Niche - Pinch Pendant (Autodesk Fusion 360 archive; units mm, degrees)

design "Pinch" references "Luxe Single Pendant Cordset - 4ft Standard", "Niche - Chief Architect - Luxe Single Pendant Cordset", "Pinch"
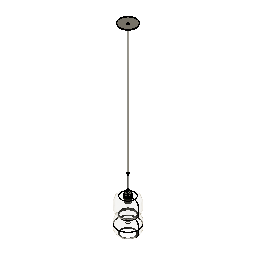
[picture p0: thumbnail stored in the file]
external_derived "ExternalDerived1"
external_derived "ExternalDerived2" bodies "Socket Body", "Shade Ring", "Shade Ring +Collar", "Socket", "Body1 (1)", "Metal Strain Relief", "Fabric Cord (1)", "Stem (Threaded)"
move "Move1"
external_derived "ExternalDerived3" bodies "T9-Bulb"
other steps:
derived_base_feature "Derived Base Feature1" bodies "Body1"
derived_base_feature "Derived Base Feature2" bodies "Socket Body", "Shade Ring", "Shade Ring +Collar", "Socket", "Body1 (1)", "Metal Strain Relief", "Fabric Cord (1)", "Stem (Threaded)"
derived_base_feature "Derived Base Feature3" bodies "T9-Bulb"
named bodies: "Body1", "Socket Body", "Shade Ring", "Shade Ring +Collar", "Socket", "Body1 (1)", "Metal Strain Relief", "Fabric Cord (1)", "Stem (Threaded)", "Cap (Threaded)", "T9-Bulb"

design "Luxe Single Pendant Cordset - 4ft Standard" references "Luxe Canopy - Single Pendant Cordset"
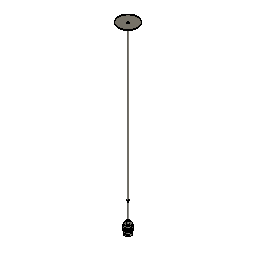
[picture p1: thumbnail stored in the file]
external_derived "ExternalDerived2" bodies "Cap (Threaded)"
move "Move1"
move "Move2"
offset_faces "OffsetFaces1" distance 1051.56
move "Move3"
move "Move4"
move "Move5"
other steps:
derived_base_feature "Derived Base Feature9" bodies "Socket Body", "Shade Ring", "Shade Ring +Collar", "Socket"
derived_base_feature "Derived Base Feature10" bodies "Body1"
derived_base_feature "Derived Base Feature12" bodies "Metal Strain Relief"
derived_base_feature "Derived Base Feature13" bodies "Fabric Cord (1)"
derived_base_feature "Derived Base Feature14" bodies "Stem (Threaded)"
derived_base_feature "Derived Base Feature15" bodies "Cap 9Threaded)", "Cap (Threaded)"
named bodies: "Socket Body", "Shade Ring", "Shade Ring +Collar", "Socket", "Metal Strain Relief", "Fabric Cord (1)", "Stem (Threaded)", "Cap 9Threaded)", "Body1", "Cap (Threaded)", "5M Set Screw"

design "Luxe Canopy - Single Pendant Cordset" references "Luxe Cordset", "M5 Set Screw", "Plastic Strain Relief", "Canopy Mounting Bar", "Canopy Mounting Bar Screw"
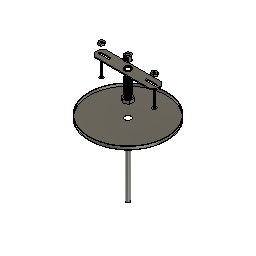
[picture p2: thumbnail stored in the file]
sketch "Sketch1" plane through (0, 0, 0) normal (0, 0, 1) x axis (1, 0, 0)
  circle C1 centre (0, 0) radius 63.5
  point P1 (0, 0)
  point P2 (0, 0)
  coincident P1 P2
  dimension "d1" diameter C1 = 127
extrude "Extrude1" new body sketch "Sketch1" along normal blind 5.08
shell "Shell1" innerThickness 0.762
hole "Hole1" HoleDepth 35.56 HoleDiameter 10.16 TipAngle 118
component_from_bodies "Body->Comp1"
component_insert "Component Insert1"
component_insert "Component Insert2"
component_insert "Component Insert3"
sketch "Sketch2" plane through (0, 0, 0) normal (0, 0, 1) x axis (1, 0, 0)
  circle C1 centre (0, 0) radius 3.175
  point P1 (0, 0)
  point P2 (0, 0)
  coincident P1 P2
  dimension "d8" diameter C1 = 6.35
extrude "Extrude2" new body sketch "Sketch2" along normal blind 127 and against normal blind 127 bodies "Fabric Cord"
component_insert "Component Insert4"
component_insert "Component Insert5"
position "Position1"
sketch "Sketch3" plane through (0, 0, 0.762) normal (0, 0, 1) x axis (-1, 0, 0)
  circle C1 centre (-0.0475, 0.2257) radius 5.08
  circle C2 centre (0, 0) radius 62.738
  circle C3 centre (0, 0) radius 4.826
  concentric C2 C3
  dimension "d13" diameter C3 = 9.652
extrude "Extrude3" new body sketch "Sketch3" profile of C3 along normal blind 25.4 bodies "Threaded Nipple"
shell "Shell2" innerThickness 1.27
thread "Thread1"
sketch "Sketch5" plane through (0, 0, 127) normal (0, 0, 1) x axis (-1, 0, 0)
  line L1 (-6.8191, 3.937) -> (0, 7.874)
  line L2 (-6.8191, -3.937) -> (-6.8191, 3.937)
  line L3 (0, -7.874) -> (-6.8191, -3.937)
  line L4 (6.8191, -3.937) -> (0, -7.874)
  line L5 (6.8191, 3.937) -> (6.8191, -3.937)
  line L6 (0, 7.874) -> (6.8191, 3.937)
  circle C1 centre (0, 0) radius 3.175
  point P2 (0, 0)
  point P9 (0, 0)
  point P3 (0, 7.874)
  coincident P2 P9
  dimension "d20" distance P3 P9 = 7.874
extrude "Extrude4" new body sketch "Sketch5" along normal blind 5.08 bodies "Hex Nut"
move "Move1"
thread "Thread2"
move "Move2" TranslateX 0 TranslateY 0 TranslateZ -55.88
move "Move3" TranslateX 0 TranslateY 0 TranslateZ 60.96
position "Position2"
sketch "Sketch6" plane through (0, 0, 0) normal (0, 0, 1) x axis (1, 0, 0)
  circle C1 centre (0, 0) radius 9.525
  point P1 (0, 0)
  point P2 (0, 0)
  coincident P1 P2
  dimension "d29" diameter C1 = 19.05
extrude "Extrude5" new body sketch "Sketch6" along normal blind 16.129 bodies "Metal Strain Relief"
move "Move4" TranslateX 0 TranslateY 0 TranslateZ -86.36
hole "Hole2" HoleDepth 10.16 HoleDiameter 5.08 TipAngle 118
hole "Hole3" HoleDepth 4.064 HoleDiameter 7.62 TipAngle 180
hole "Hole4" HoleDepth 12.192 HoleDiameter 9.144 TipAngle 180
thread "Thread3" ThreadOffset 0 ThreadLength 6.096
move "Move1" TranslateX 0 TranslateY 0 TranslateZ 68.58
move "Move5" TranslateX 0 TranslateY 0 TranslateZ 138.43
component_insert "Component Insert6"
external_derived "ExternalDerived1" bodies "5M Set Screw"
move "Move6" TranslateX 0 TranslateY 0 TranslateZ -185.42
copy_paste_bodies "CopyPasteBodies1"
move "Move7" TranslateX 0 TranslateY 0 TranslateZ -12.7
offset_faces "OffsetFaces1" distance -152.4
move "Move8"
component_from_bodies "Body->Comp2"
component_from_bodies "Body->Comp3"
component_from_bodies "Body->Comp4"
component_from_bodies "Body->Comp5"
hole "Hole1" HoleDepth 25.4 HoleDiameter 6.35 TipAngle 180
sketch "Sketch7" plane through (0, 0, 0) normal (0, 0, 1) x axis (1, 0, 0)
  line L1 (49.784, 3.9595) -> (52.07, 0)
  line L2 (45.212, 3.9595) -> (49.784, 3.9595)
  line L3 (42.926, 0) -> (45.212, 3.9595)
  line L4 (45.212, -3.9595) -> (42.926, 0)
  line L5 (49.784, -3.9595) -> (45.212, -3.9595)
  line L6 (52.07, 0) -> (49.784, -3.9595)
  point P2 (52.07, 0)
  point P8 (47.498, 0)
  dimension "d63" distance P2 P8 = 4.572
extrude "Extrude6" new body sketch "Sketch7" along normal blind 3.175 bodies "Mounting Hex Nut"
hole "Hole5" HoleDepth 25.4 HoleDiameter 3.81 TipAngle 180
thread "Thread4"
move "Move9"
component_from_bodies "Body->Comp6"
copy_paste "CopyPaste1"
move "Move10"
derived_base_feature "Derived Base Feature3" bodies "Stem (Threaded)", "Cap 9Threaded)"
move "Move11"
component_from_bodies "Body->Comp7"
component_from_bodies "Body->Comp8"
component_from_bodies "Body->Comp9"
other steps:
base_feature "Base Feature1"
base_feature "Base Feature1" bodies "Stem (Threaded)"
base_feature "Base Feature1" bodies "Cap 9Threaded)"
base_feature "Base Feature1" bodies "Fabric Cord"
base_feature "Base Feature1" bodies "Metal Strain Relief"
base_feature "Base Feature1" bodies "Mounting Hex Nut"
base_feature "Base Feature1" bodies "Hex Nut"
base_feature "Base Feature1" bodies "Fabric Cord (1)"
base_feature "Base Feature1" bodies "Threaded Nipple"
derived_base_feature "Derived Base Feature1" bodies "Socket Body", "Shade Ring", "Shade Ring +Collar", "Socket", "Rigid Stem"
derived_base_feature "Derived Base Feature2" bodies "5M Set Screw"
base_feature "Base Feature1" bodies "Fabric Cord", "Fabric Cord (1)"
create_component "CreateComponent1"
remove_body "RemoveBody1"
create_component "CreateComponent2"
remove_body "RemoveBody2"
create_component "CreateComponent3"
remove_body "RemoveBody3"
create_component "CreateComponent4"
remove_body "RemoveBody4"
create_component "CreateComponent5"
remove_body "RemoveBody5"
create_component "CreateComponent6"
remove_body "RemoveBody6"
create_component "CreateComponent7"
remove_body "RemoveBody7"
create_component "CreateComponent8"
remove_body "RemoveBody8"
create_component "CreateComponent9"
remove_body "RemoveBody9"
named bodies: "Fabric Cord", "Threaded Nipple", "Hex Nut", "Metal Strain Relief", "Socket Body", "Shade Ring", "Shade Ring +Collar", "Socket", "Rigid Stem", "5M Set Screw", "Fabric Cord (1)", "Mounting Hex Nut", "Stem (Threaded)", "Cap 9Threaded)"

design "M5 Set Screw"
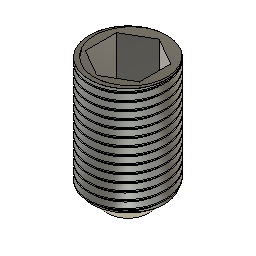
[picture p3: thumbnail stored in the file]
sketch "Sketch1" plane through (0, 0, 0) normal (0, 0, 1) x axis (1, 0, 0)
  circle C1 centre (0, 0) radius 2.5
  point P1 (0, 0)
  point P2 (0, 0)
  coincident P1 P2
  dimension "d1" diameter C1 = 5
extrude "Extrude1" new body sketch "Sketch1" along normal blind 8
sketch "Sketch2" plane through (0, 0, 8) normal (0, 0, 1) x axis (-1, 0, 0)
  line L1 (-1.7321, 1) -> (0, 2)
  line L2 (-1.7321, -1) -> (-1.7321, 1)
  line L3 (0, -2) -> (-1.7321, -1)
  line L4 (1.7321, -1) -> (0, -2)
  line L5 (1.7321, 1) -> (1.7321, -1)
  line L6 (0, 2) -> (1.7321, 1)
  circle C1 centre (0, 0) radius 2.5
  point P2 (0, 0)
  point P9 (0, 0)
  coincident P2 P9
extrude "Extrude2" cut sketch "Sketch2" profile of L1 L2 L3 L4 L5 L6 against normal blind 3
thread "Thread1" ThreadOffset 0.99 ThreadLength 7
chamfer "Chamfer1" distance 1.15

design "Luxe Cordset" references "M5 Set Screw"
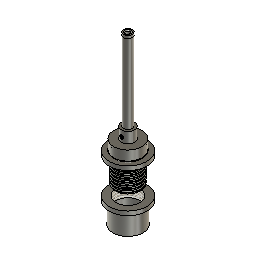
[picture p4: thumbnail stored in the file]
sketch "Sketch1" plane through (0, 0, 0) normal (0, 0, 1) x axis (1, 0, 0)
  circle C1 centre (0, 0) radius 20.6
  point P1 (0, 0)
  point P2 (0, 0)
  coincident P1 P2
  dimension "d11" diameter C1 = 41.2
extrude "Extrude1" new body sketch "Sketch1" along normal blind 14 bodies "Socket Body"
sketch "Sketch2" plane through (0, 0, 14) normal (0, 0, 1) x axis (-1, 0, 0)
  circle C1 centre (0, 0) radius 20.6
  circle C2 centre (0, 0) radius 9.6
  concentric C1 C2
  dimension "d3" diameter C2 = 19.2
extrude "Extrude2" add sketch "Sketch2" profile of C2 along normal blind 15.75
sketch "Sketch3" plane through (0, 0, 29.75) normal (0, 0, 1) x axis (-1, 0, 0)
  circle C1 centre (0, 0) radius 9.6
  circle C2 centre (0, 0) radius 5.75
  concentric C1 C2
  dimension "d6" diameter C2 = 11.5
extrude "Extrude3" new body sketch "Sketch3" profile of C2 along normal blind 114 bodies "Rigid Stem"
move "Move1"
sketch "Sketch4" plane through (0, 0, 203.75) normal (0, 0, 1) x axis (-1, 0, 0)
  circle C1 centre (0, 0) radius 5.75
  circle C2 centre (0, 0) radius 27.5
  dimension "d10" diameter C2 = 55
extrude "Extrude4" new body sketch "Sketch4" profile of C2 along normal blind 6 bodies "Shade Ring"
hole "Hole1" HoleDepth 25 HoleDiameter 42.75 TipAngle 118
sketch "Sketch5" plane through (0, 0, 0) normal (0, 0, 1) x axis (1, 0, 0)
  circle C1 centre (0, 0) radius 22
  point P1 (0, 0)
  point P2 (0, 0)
  coincident P1 P2
  dimension "d18" diameter C1 = 44
move "Move2"
copy_paste_bodies "CopyPasteBodies1"
move "Move3"
sketch "Sketch6" plane through (0, 0, 60) normal (0, 0, -1) x axis (1, 0, 0)
  circle C1 centre (0, 0) radius 20.6
  circle C2 centre (0, 0) radius 21.375
  circle C3 centre (0, 0) radius 20
  concentric C1 C2
  concentric C1 C3
  dimension "d21" diameter C2 = 42.75
  dimension "d24" diameter C3 = 40
cylinder_primitive "CylinderPrimitive1" Height 8 Diameter 42.75
thread "Thread1"
thread "Thread3"
hole "Hole2" HoleDepth 18 HoleDiameter 39 TipAngle 180
move "Move4"
move "Move5"
move "Move6"
hole "Hole3" HoleDepth 114 HoleDiameter 7.6 TipAngle 180
derived_base_feature "Derived Base Feature" bodies "Socket"
move "Move7"
scale "Scale1" ScaleX 1.2 ScaleY 1.2
move "Move8"
sketch "Sketch8" plane through (0, 0, -23.9827) normal (0, 0, -1) x axis (1, 0, 0)
  circle C1 centre (0, -0.036) radius 27.5
  circle C2 centre (0, -0.036) radius 22
  circle C3 centre (0, -0.036) radius 19.5
  dimension "d36" diameter C2 = 44
  dimension "d42" = -2.5
extrude "Extrude7" add sketch "Sketch8" profile of C2 C3 along normal blind 30
offset_faces "OffsetFaces1" distance 2.75
offset_faces "OffsetFaces2" distance -9
thread "Thread2"
move "Move9"
move "Move10"
move "Move11"
scale "Scale2" ScaleZ 1.2
move "Move12"
move "Move13"
move "Move14"
move "Move15"
move "Move16"
split_face "SplitFace1"
move "Move17"
move "Move18"
move "Move19"
move "Move20"
move "Move21"
move "Move22"
move "Move23"
move "Move24"
move "Move25"
move "Move26"
move "Move27"
thread "Thread4"
move "Move28"
move "Move29"
move "Move30"
hole "Hole4" HoleDepth 21 HoleDiameter 39.35 TipAngle 180
hole "Hole5" HoleDepth 9 HoleDiameter 5 TipAngle 180
move "Move31"
move "Move32"
hole "Hole6" HoleDepth 20 HoleDiameter 10 TipAngle 180
move_face "MoveFace3"
move "Move33"
move "Move34"
move "Move35"
move "Move36"
move "Move37"
thread "Thread5" ThreadOffset 0 ThreadLength 6
thread "Thread6" ThreadOffset 0 ThreadLength 6
move "Move38"
move "Move39"
move "Move40"
move "Move41"
component_insert "Component Insert"
thread "Thread7" ThreadOffset 0.5 ThreadLength 5.337
chamfer "Chamfer1" distance 0.5 distance 0.35
sketch "Sketch12" plane through (0, 0, 0) normal (0, 0, 1) x axis (1, 0, 0)
  circle C1 centre (0, 0) radius 6.35
  dimension "d60" diameter C1 = 12.7
extrude "Extrude8" new body sketch "Sketch12" along normal blind 115 bodies "Stem (Threaded)"
hole "Hole7" HoleDepth 115 HoleDiameter 9.65 TipAngle 118
thread "Thread8" ThreadOffset 0 ThreadLength 12.5
thread "Thread9" ThreadOffset 0 ThreadLength 12.5
sketch "Sketch13" plane through (0, 0, 0) normal (0, 0, 1) x axis (1, 0, 0)
  circle C1 centre (0, 0) radius 6.35
  point P1 (0, 0)
  point P2 (0, 0)
  coincident P1 P2
  dimension "d70" diameter C1 = 12.7
extrude "Extrude9" new body sketch "Sketch13" along normal blind 4 bodies "Cap 9Threaded)"
sketch "Sketch14" plane through (0, 0, 4) normal (0, 0, 1) x axis (-1, 0, 0)
  circle C1 centre (0, 0) radius 6.35
  circle C2 centre (0, 0) radius 4.5
  concentric C1 C2
  dimension "d73" diameter C2 = 9
extrude "Extrude10" add sketch "Sketch14" profile of C2 against normal blind 14
thread "Thread10"
hole "Hole8" HoleDepth 115 HoleDiameter 6.5 TipAngle 118 CSDiameter 9 CSAngle 90
move "Move42"
move "Move43"
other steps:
base_feature "Base Feature" bodies "Shade Ring +Collar"
named bodies: "Socket Body", "Shade Ring", "Shade Ring +Collar", "Socket", "Rigid Stem", "Stem (Threaded)", "Cap 9Threaded)"

design "Niche_Pinch_Single_Pendant"
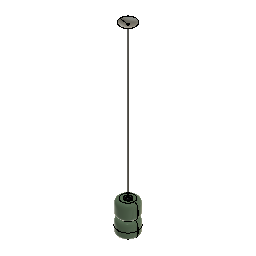
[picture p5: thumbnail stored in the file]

design "Niche - Chief Architect - Luxe Single Pendant Cordset"
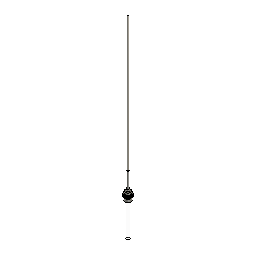
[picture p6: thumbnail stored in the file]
derived_base_feature "Derived Base Feature" bodies "Socket Body", "Shade Ring", "Shade Ring +Collar", "Socket", "Canopy", "Metal Strain Relief", "Fabric Cord (1)", "Stem (Threaded)"
remove_body "RemoveBody1"
remove_body "RemoveBody2"
split "Split1" bodies "Socket Body (1)"
remove_body "RemoveBody3"
align "Align1"
hole "Hole1" HoleDepth 19.05 HoleDiameter 8.89 TipAngle 118
combine "Combine1" bodies "Shade Ring"
split "Split2" bodies "Socket (1)"
remove_body "RemoveBody4"
split "Split3" bodies "Fabric Cord (1) (1)"
remove_body "RemoveBody5"
combine "Combine2" bodies "Socket Body"
align "Align2"
combine "Combine3" bodies "Metal Strain Relief"
sketch "Sketch1" plane through (0, 0, 0) normal (0, 1, 0) x axis (1, 0, 0)
  line L1 (13.1098, 24.9049) -> (-12.2902, 24.9049)
  line L2 (18.1898, 37.1766) -> (18.1898, 29.9849)
  line L3 (-17.3702, 29.9849) -> (-17.3702, 36.7132)
  line L4 (0, 132.969) -> (0, 24.9049)
  arc A1 centre (0, 86.36) radius 46.609 clockwise from (-22.6031, 45.5985) to (23.276, 45.979)
  arc A2 centre (-27.5302, 36.7132) radius 10.16 clockwise from (-22.6031, 45.5985) to (-17.3702, 36.7132)
  arc A3 centre (28.3498, 37.1766) radius 10.16 clockwise from (18.1898, 37.1766) to (23.276, 45.979)
  arc A4 centre (-12.2902, 29.9849) radius 5.08 clockwise from (-12.2902, 24.9049) to (-17.3702, 29.9849)
  arc A5 centre (13.1098, 29.9849) radius 5.08 clockwise from (18.1898, 29.9849) to (13.1098, 24.9049)
  point P5 (18.1898, 43.4469)
  point P3 (-17.3702, 24.9049)
  point P4 (18.1898, 24.9049)
  point P18 (0, 24.9049)
  point P19 (0, 132.969)
  horizontal L1
  vertical L2
  vertical L3
  tangent A1 A2
  tangent L3 A2
  coincident P5 L2
  coincident P5 A1
  tangent L2 A3
  tangent A1 A3
  equal A2 A3
  coincident P3 L1
  coincident P3 L3
  tangent L1 A4
  tangent L3 A4
  coincident P4 L1
  coincident P4 L2
  tangent L1 A5
  tangent L2 A5
  coincident L1 P18
  coincident A1 P19
  perpendicular L1 L4
  dimension "d4" diameter A1 = 93.218
  dimension "d5" distance P3 P4 = 35.56
  dimension "d6" distance P4 P5 = 18.542
  dimension "d7" radius A2 = 10.16
  dimension "d8" radius A4 = 5.08
  dimension "d9" radius A5 = 5.08
revolve "Revolve1" sketch "Sketch1" AlongAngle 360 bodies "G30-Bulb"
move "Move1"
sketch "Sketch2" plane through (0, 0, 0) normal (0, 1, 0) x axis (1, 0, 0)
  line L1 (12.7, 0) -> (-12.7, 0)
  line L2 (12.7, 152.4) -> (12.7, 0)
  line L3 (-12.7, 0) -> (-12.7, 152.4)
  line L4 (0, 165.1) -> (0, 0)
  arc A1 centre (0, 152.4) radius 12.7 clockwise from (-12.7, 152.4) to (12.7, 152.4)
  point P1 (0, 0)
  point P7 (0, 0)
  point P8 (0, 165.1)
  horizontal L1
  vertical L2
  vertical L3
  coincident P1 P7
  midpoint A1 P8
  perpendicular L1 L4
revolve "Revolve2" sketch "Sketch2" AlongAngle 360 bodies "T9-Bulb"
move "Move2"
sketch "Sketch3" plane through (0, 0, 0) normal (0, 1, 0) x axis (1, 0, 0)
  line L1 (12.7, 0) -> (-12.7, 0)
  line L2 (12.7, 254) -> (12.7, 0)
  line L3 (-12.7, 0) -> (-12.7, 254)
  line L4 (0, 266.7) -> (0, 0)
  arc A1 centre (0, 254) radius 12.7 clockwise from (-12.7, 254) to (12.7, 254)
  point P1 (0, 0)
  point P7 (0, 0)
  point P8 (0, 266.7)
  horizontal L1
  vertical L2
  vertical L3
  coincident P1 P7
  midpoint A1 P8
  perpendicular L1 L4
revolve "Revolve3" sketch "Sketch3" AlongAngle 360 bodies "T8-Bulb"
move "Move3"
move "Move4"
move "Move5"
sketch "Sketch4" plane through (0, 0, 0) normal (0, 1, 0) x axis (1, 0, 0)
  line L1 (15.875, -8.763) -> (-15.875, -8.763)
  line L2 (15.875, 22.987) -> (15.875, -8.763)
  line L3 (-15.875, 22.987) -> (15.875, 22.987)
  line L4 (-15.875, -8.763) -> (-15.875, 22.987)
  line L5 (0, 22.987) -> (0, -8.763)
  point P6 (0, -8.763)
  point P7 (0, 22.987)
  point P2 (-15.875, -8.763)
  point P3 (15.875, -8.763)
  point P5 (-15.875, 22.987)
  horizontal L1
  vertical L2
  horizontal L3
  vertical L4
  midpoint L1 P6
  midpoint L3 P7
  dimension "d13" distance P2 P3 = 31.75
  dimension "d14" distance P2 P5 = 31.75
revolve "Revolve4" sketch "Sketch4" AlongAngle 360 bodies "Bulb Extender"
move "Move6"
sketch "Sketch5" plane through (0, 0, 0) normal (0, 1, 0) x axis (1, 0, 0)
  line L1 (-12.7, 35.56) -> (12.7, 35.56)
  line L2 (-12.7, 5.08) -> (-12.7, 35.56)
  line L3 (12.7, 5.08) -> (-12.7, 5.08)
  line L4 (12.7, 35.56) -> (12.7, 5.08)
  line L5 (-12.7, 5.08) -> (12.7, 35.56)
  line L6 (12.7, 5.08) -> (-12.7, 35.56)
  line L7 (0, 35.56) -> (0, 5.08)
  point P6 (0, 20.32)
  point P7 (0, 5.08)
  point P8 (0, 35.56)
  horizontal L1
  perpendicular L1 L2
  parallel L1 L3
  parallel L2 L4
  coincident L5 P6
  coincident L6 P6
  midpoint L3 P7
  midpoint L1 P8
revolve "Revolve5" sketch "Sketch5" AlongAngle 360 bodies "Y-Spliter"
sketch "Sketch6" plane through (0, 0, 0) normal (0, 1, 0) x axis (1, 0, 0)
  line L1 (-55.88, 64.9514) -> (-21.59, 64.9514)
  line L2 (-55.88, 35.7414) -> (-55.88, 64.9514)
  line L3 (-21.59, 35.7414) -> (-55.88, 35.7414)
  line L4 (-21.59, 64.9514) -> (-21.59, 35.7414)
  line L5 (-55.88, 35.7414) -> (-21.59, 64.9514)
  line L6 (-21.59, 35.7414) -> (-55.88, 64.9514)
  line L7 (-38.735, 64.9514) -> (-38.735, 35.7414)
  point P6 (-38.735, 50.3464)
  point P7 (-38.735, 35.7414)
  point P8 (-38.735, 64.9514)
  point P4 (-55.88, 35.7414)
  point P5 (-21.59, 35.7414)
  point P2 (-21.59, 64.9514)
  horizontal L1
  perpendicular L1 L2
  parallel L1 L3
  parallel L2 L4
  coincident L5 P6
  coincident L6 P6
  midpoint L3 P7
  midpoint L1 P8
  dimension "d17" distance P4 P5 = 34.29
  dimension "d18" distance P2 P5 = 29.21
revolve "Revolve6" sketch "Sketch6" AlongAngle 360
chamfer "Chamfer1" distance 7.62
move "Move7"
mirror "Mirror1" mirrorStitchTolerance 0.1016
move "Move8"
combine "Combine4"
move "Move9"
sketch "Sketch7" plane through (0, 0, 0) normal (0, 1, 0) x axis (1, 0, 0)
  line L1 (-15.24, 40.64) -> (-15.24, 48.1816)
  line L2 (12.7, 38.1) -> (-12.7, 38.1)
  line L3 (15.24, 48.1816) -> (15.24, 40.64)
  line L4 (0, 100.1623) -> (0, 38.1)
  arc A1 centre (0, 76.2) radius 23.9623 clockwise from (-19.7282, 62.5988) to (19.7282, 62.5988)
  arc A2 centre (-40.64, 48.1816) radius 25.4 clockwise from (-19.7282, 62.5988) to (-15.24, 48.1816)
  arc A3 centre (40.64, 48.1816) radius 25.4 clockwise from (15.24, 48.1816) to (19.7282, 62.5988)
  arc A4 centre (-12.7, 40.64) radius 2.54 clockwise from (-12.7, 38.1) to (-15.24, 40.64)
  arc A5 centre (12.7, 40.64) radius 2.54 clockwise from (15.24, 40.64) to (12.7, 38.1)
  point P15 (0, 38.1)
  point P16 (0, 100.1623)
  parallel L1 L3
  tangent A1 A2
  tangent L1 A2
  tangent A1 A3
  tangent L3 A3
  tangent L1 A4
  tangent L2 A4
  tangent L2 A5
  tangent L3 A5
  midpoint L2 P15
  midpoint A1 P16
  perpendicular L2 L4
  dimension "d23" radius A2 = 25.4
  dimension "d24" radius A3 = 25.4
  dimension "d25" radius A4 = 2.54
  dimension "d26" radius A5 = 2.54
revolve "Revolve7" sketch "Sketch7" AlongAngle 360 bodies "A15-Bulb"
move "Move10"
copy_paste_bodies "CopyPasteBodies1"
copy_paste_bodies "CopyPasteBodies2"
move "Move11"
mirror "Mirror2" mirrorStitchTolerance 0.1016 bodies "A15-Bulb (1) (1)"
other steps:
base_feature "Base Feature1" bodies "Y-Spliter", "Bulb Extender", "Y-Spliter (1)", "Bulb Extender (1)"
base_feature "Base Feature2" bodies "A15-Bulb", "A15-Bulb (1)"
named bodies: "Socket Body", "Shade Ring", "Shade Ring +Collar", "Socket", "Canopy", "Metal Strain Relief", "Fabric Cord (1)", "Stem (Threaded)", "Adapter", "5M Set Screw", "Body1 (1)", "Socket Body (1)", "Socket (1)", "Fabric Cord (1) (1)", "G30-Bulb", "T9-Bulb", "T8-Bulb", "Bulb Extender", "Y-Spliter", "A15-Bulb", "Y-Spliter (1)", "Bulb Extender (1)", "A15-Bulb (1)", "A15-Bulb (1) (1)"

design "Plastic Strain Relief"
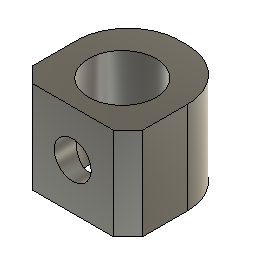
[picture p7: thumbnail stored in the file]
base_feature "Base Feature" bodies "strainrelief"
named bodies: "strainrelief"

design "Canopy Mounting Bar Screw"
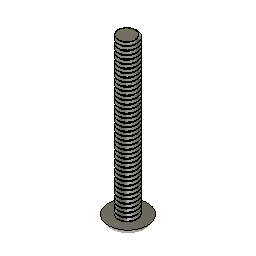
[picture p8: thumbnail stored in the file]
base_feature "Base Feature" bodies "screw1"
named bodies: "screw1"

design "Canopy Mounting Bar"
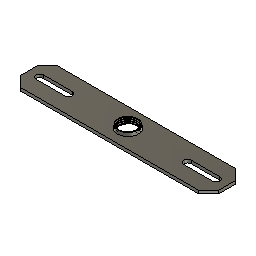
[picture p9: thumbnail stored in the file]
base_feature "Base Feature" bodies "mountingbar"
named bodies: "mountingbar"

design "Pinch" references "Niche_Pinch_Single_Pendant"
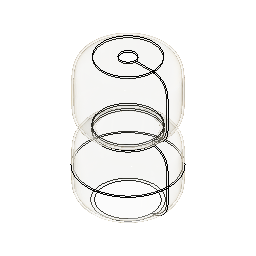
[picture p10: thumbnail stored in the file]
external_derived "ExternalDerived"
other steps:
derived_base_feature "Derived Base Feature" bodies "Body1"
named bodies: "Body1"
